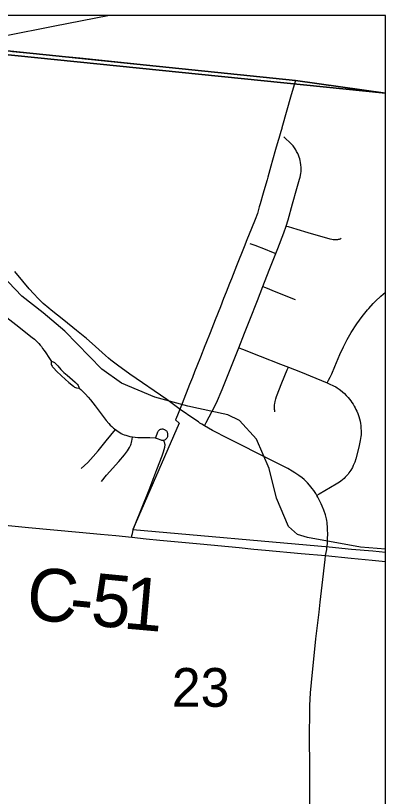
# Model space of a CAD drawing. Extents: x 0 to 34, y 0 to 22.
# Drawn here: x 8.313 to 8.712, y 20.263 to 21.106 of the extents above; entities that cross this region are included whole.
import ezdxf

# ---------------------------------------------------------------- set-up
doc = ezdxf.new("R2010")
doc.units = 0
for name, color, linetype in [('GM_X_City_Street', 7, 'Continuous'), ('GM_X_Corporation', 7, 'Continuous'), ('GM_X_County_Road', 7, 'Continuous'), ('GM_X_County_Road_Text', 7, 'Continuous'), ('GM_X_Interstate_Route', 7, 'Continuous'), ('GM_X_Minor_River', 7, 'Continuous'), ('GM_X_Section_Text', 7, 'Continuous')]:
    doc.layers.add(name, color=color, linetype=linetype)

msp = doc.modelspace()

# ---------------------------------------------------------------- linework, layer by layer
at = {"layer": 'GM_X_City_Street'}
for points in [[(8.51668, 20.66289), (8.5187, 20.66664), (8.52515, 20.6786), (8.52968, 20.6878), (8.53587, 20.70225), (8.55364, 20.74723), (8.55986, 20.76297), (8.56561, 20.7774), (8.57394, 20.79813), (8.57968, 20.8133), (8.5814, 20.81786), (8.58741, 20.83288), (8.5937, 20.84907), (8.5958, 20.85446), (8.60235, 20.87145), (8.60472, 20.87865), (8.60695, 20.88539), (8.61178, 20.90245), (8.6165, 20.91928), (8.61933, 20.92925), (8.61991, 20.93156), (8.62065, 20.93531), (8.62088, 20.93739), (8.621, 20.9397), (8.62095, 20.9417), (8.62076, 20.94489), (8.62046, 20.94735), (8.62008, 20.94924), (8.61955, 20.95123), (8.61895, 20.95313), (8.61805, 20.95532), (8.6173, 20.95697), (8.61615, 20.95927), (8.61534, 20.96078), (8.61461, 20.96197), (8.61393, 20.96297), (8.61308, 20.96419), (8.61234, 20.9651), (8.61128, 20.96624), (8.60955, 20.96799), (8.60346, 20.9738), (8.60225, 20.97493)], [(8.60472, 20.87865), (8.60708, 20.87797), (8.61638, 20.87532), (8.62825, 20.87166), (8.6521, 20.86477), (8.65396, 20.86437), (8.65573, 20.86414), (8.65749, 20.86399), (8.65873, 20.86397), (8.66064, 20.86414), (8.66147, 20.8643), (8.66234, 20.86455), (8.66314, 20.86484), (8.66438, 20.86544)], [(8.56585, 20.85991), (8.57112, 20.85799), (8.58211, 20.85358), (8.58908, 20.85086), (8.5937, 20.84907)], [(8.26292, 20.8211), (8.26641, 20.81677), (8.2702, 20.8118), (8.27768, 20.80174), (8.27887, 20.80025), (8.28028, 20.79864), (8.28176, 20.79723), (8.28354, 20.79567), (8.29194, 20.78906), (8.3036, 20.78), (8.31648, 20.76974), (8.32398, 20.76383), (8.33097, 20.75829), (8.33325, 20.75629), (8.33506, 20.75474), (8.3367, 20.75317), (8.33806, 20.75174), (8.33946, 20.75009), (8.34082, 20.74837), (8.34213, 20.74652), (8.34384, 20.74408), (8.34559, 20.7416), (8.34886, 20.73658), (8.35165, 20.7323)], [(8.57968, 20.8133), (8.58145, 20.81259), (8.58445, 20.81139), (8.59193, 20.80826), (8.61465, 20.79943)], [(8.64908, 20.70924), (8.6507, 20.71229), (8.65228, 20.71546), (8.65406, 20.71916), (8.65729, 20.72688), (8.6627, 20.73983), (8.66663, 20.74829), (8.67063, 20.75601), (8.67501, 20.76354), (8.68108, 20.77294), (8.68688, 20.78104), (8.69117, 20.78647), (8.69244, 20.78798), (8.69399, 20.78968), (8.69887, 20.7951), (8.70109, 20.79732), (8.70712, 20.8029), (8.71189, 20.80715)], [(8.55364, 20.74723), (8.55771, 20.7456), (8.57673, 20.73799), (8.59873, 20.72944), (8.60722, 20.72613), (8.62017, 20.72108), (8.63689, 20.71433), (8.64908, 20.70924), (8.65136, 20.70828), (8.65609, 20.70602), (8.65832, 20.70482), (8.65981, 20.70393), (8.66188, 20.70255), (8.66363, 20.70124), (8.66556, 20.69962), (8.66764, 20.69774), (8.66957, 20.6958), (8.67165, 20.69348), (8.67319, 20.69164), (8.67448, 20.69004), (8.67585, 20.68812), (8.67705, 20.68631), (8.67826, 20.68426), (8.67939, 20.68217), (8.68018, 20.68055), (8.68097, 20.67878), (8.68202, 20.67617), (8.68315, 20.67305), (8.68398, 20.67031), (8.68455, 20.66796), (8.68506, 20.66525), (8.68532, 20.66338), (8.68553, 20.66111), (8.68576, 20.65667), (8.68561, 20.65321), (8.68541, 20.65119), (8.68479, 20.64718), (8.68332, 20.63987), (8.68004, 20.62719), (8.67882, 20.62359), (8.678, 20.62146), (8.67733, 20.61994), (8.67633, 20.61793), (8.67457, 20.61502), (8.6726, 20.61204), (8.67163, 20.61078), (8.6699, 20.60872), (8.66869, 20.60742), (8.6673, 20.60608), (8.66575, 20.60473), (8.66386, 20.60325), (8.66239, 20.60217), (8.65883, 20.59985), (8.64037, 20.589), (8.63794, 20.58756)], [(8.35165, 20.7323), (8.35149, 20.73156), (8.35137, 20.73082), (8.35137, 20.73004), (8.35146, 20.72921), (8.35178, 20.72831), (8.35236, 20.72745), (8.35299, 20.72664), (8.35429, 20.72511), (8.35725, 20.7219), (8.36256, 20.71682), (8.3706, 20.70983), (8.37538, 20.70554), (8.37644, 20.70476), (8.37755, 20.70423), (8.3787, 20.7039), (8.38147, 20.70348)], [(8.35165, 20.7323), (8.35252, 20.73218), (8.35344, 20.73197), (8.3543, 20.73164), (8.35494, 20.73119), (8.35565, 20.73057), (8.35643, 20.72971), (8.3584, 20.72757), (8.36197, 20.72363), (8.36517, 20.72058), (8.36855, 20.71748), (8.3771, 20.71019), (8.37837, 20.70912), (8.37932, 20.70813), (8.37991, 20.70737), (8.38034, 20.70657), (8.38073, 20.70561), (8.38147, 20.70348)], [(8.59279, 20.67789), (8.59253, 20.67936), (8.59237, 20.68033), (8.59224, 20.68139), (8.59216, 20.68203), (8.59213, 20.68276), (8.59212, 20.68421), (8.59229, 20.6857), (8.59253, 20.68697), (8.59297, 20.68905), (8.59376, 20.69197), (8.59461, 20.69462), (8.60026, 20.70914), (8.60605, 20.7233), (8.60722, 20.72613)], [(8.38147, 20.70348), (8.3833, 20.70197), (8.38526, 20.70024), (8.38831, 20.69719), (8.39139, 20.6938), (8.39389, 20.6909), (8.39883, 20.68459), (8.41075, 20.66879), (8.41345, 20.66545), (8.41509, 20.66371), (8.41677, 20.66215), (8.41879, 20.66034), (8.42072, 20.65878)], [(8.38382, 20.61666), (8.39079, 20.62319), (8.3967, 20.62967), (8.40195, 20.63602), (8.41079, 20.64676), (8.42072, 20.65878)], [(8.42072, 20.65878), (8.42207, 20.65779), (8.42363, 20.65675), (8.42559, 20.6555), (8.42693, 20.65471), (8.42839, 20.65401), (8.43011, 20.65329), (8.43196, 20.65268), (8.43399, 20.652), (8.4364, 20.65139), (8.43896, 20.65089)], [(8.47295, 20.64737), (8.47392, 20.64778), (8.47453, 20.64813), (8.47512, 20.64853), (8.47568, 20.64902), (8.47619, 20.64955), (8.47659, 20.65017), (8.4769, 20.6508), (8.47713, 20.65145), (8.47729, 20.65214), (8.47739, 20.65292), (8.47736, 20.65368), (8.47719, 20.65456), (8.47696, 20.6552), (8.4767, 20.65586), (8.47641, 20.65645), (8.47603, 20.65702), (8.47557, 20.65757), (8.47504, 20.65799), (8.47451, 20.65832), (8.47393, 20.65861), (8.47286, 20.65894), (8.47215, 20.6591), (8.47134, 20.6592), (8.47063, 20.65915), (8.46978, 20.659), (8.46897, 20.65877), (8.4683, 20.65839), (8.46726, 20.65754), (8.46683, 20.65706), (8.46645, 20.65643), (8.46613, 20.65585), (8.46384, 20.65008)], [(8.40553, 20.60275), (8.41104, 20.60947), (8.42427, 20.62431), (8.43032, 20.63138), (8.43362, 20.63587), (8.43482, 20.6377), (8.4359, 20.63957), (8.43663, 20.64098), (8.43725, 20.64237), (8.43765, 20.64345), (8.43802, 20.64472), (8.43839, 20.64653), (8.43864, 20.64822), (8.43896, 20.65089)], [(8.43896, 20.65089), (8.44188, 20.65065), (8.4449, 20.65041), (8.44869, 20.65024), (8.45797, 20.65009), (8.46339, 20.6498), (8.4638, 20.64975), (8.46403, 20.64973), (8.46469, 20.64961), (8.46559, 20.64932), (8.46966, 20.64763), (8.47042, 20.64741), (8.47104, 20.6473), (8.4717, 20.64728), (8.47295, 20.64737)], [(8.43823, 20.54259), (8.43848, 20.54435), (8.43899, 20.5467), (8.43989, 20.55047), (8.44202, 20.55645), (8.45721, 20.59387), (8.4622, 20.60709), (8.46551, 20.61564), (8.47099, 20.63063), (8.47239, 20.63461), (8.4733, 20.63737), (8.47401, 20.63999), (8.47416, 20.6409), (8.4742, 20.64168), (8.4742, 20.64246), (8.47408, 20.64328), (8.47392, 20.64407), (8.47367, 20.64493), (8.47338, 20.64604), (8.47295, 20.64737)]]:
    msp.add_lwpolyline(points, dxfattribs=at)
at = {"layer": 'GM_X_Corporation'}
for points in [[(8.71189, 14.30587), (8.71189, 21.10587), (4.05187, 21.10587)], [(8.71189, 14.30587), (8.71189, 21.02216), (8.61486, 21.03591), (8.24427, 21.07383), (8.1735, 21.08097), (8.1315, 21.08535), (8.11104, 21.08726), (7.91119, 21.10587), (4.05187, 21.10587)], [(8.30961, 21.06701), (8.38217, 21.06041), (8.61486, 21.03592), (8.61036, 21.02015), (8.60025, 20.98476), (8.60003, 20.98398), (8.59911, 20.98073), (8.59696, 20.97312), (8.59632, 20.97091), (8.59352, 20.96113), (8.59028, 20.94979), (8.58839, 20.94316), (8.58502, 20.93135), (8.58423, 20.92859), (8.58184, 20.92023), (8.58007, 20.91402), (8.57678, 20.90248), (8.57591, 20.89945), (8.57548, 20.89795), (8.5738, 20.89203), (8.57126, 20.88563), (8.56428, 20.86802), (8.56334, 20.86565), (8.56257, 20.8637), (8.55966, 20.85635), (8.55141, 20.83555), (8.54583, 20.82147), (8.54383, 20.81643), (8.54025, 20.80738), (8.53742, 20.80023), (8.53396, 20.7915), (8.52839, 20.77745), (8.52281, 20.76336), (8.51816, 20.75163), (8.51722, 20.74928), (8.51239, 20.73708), (8.51164, 20.73519), (8.50613, 20.72128), (8.50368, 20.71511), (8.50074, 20.70768), (8.49256, 20.68703), (8.48751, 20.67429), (8.48549, 20.6692), (8.48934, 20.66579), (8.43934, 20.55075), (8.65139, 20.53237), (8.67553, 20.52977), (8.6983, 20.52786), (8.69842, 20.52785), (8.71189, 20.52655), (8.71189, 21.10587), (8.10417, 21.10587)]]:
    msp.add_lwpolyline(points, dxfattribs=at)
for points in [[(8.71189, 21.02216), (8.71189, 21.10587), (7.91119, 21.10587), (8.11104, 21.08726), (8.1315, 21.08535), (8.1735, 21.08097), (8.24427, 21.07383), (8.61486, 21.03591)], [(8.71189, 21.0221), (8.71189, 21.10587), (8.11564, 21.10587), (8.11355, 21.08279)], [(8.71189, 20.00282), (8.71189, 21.0221), (8.11355, 21.08279), (8.01264, 20.06664)]]:
    msp.add_lwpolyline(points, close=True, dxfattribs=at)
at = {"layer": 'GM_X_County_Road'}
for points in [[(8.47599, 20.69146), (8.43622, 20.71862), (8.42291, 20.72822), (8.41572, 20.73375), (8.41326, 20.7358), (8.40983, 20.73888), (8.39576, 20.75185), (8.38949, 20.75732), (8.37873, 20.76597), (8.36519, 20.7768), (8.35123, 20.78779), (8.34884, 20.78976), (8.34278, 20.79508), (8.33723, 20.8005), (8.33256, 20.80542), (8.32764, 20.8108), (8.32065, 20.81908), (8.31231, 20.82953)], [(8.49062, 20.68058), (8.48629, 20.68369), (8.47599, 20.69146)], [(8.51668, 20.66289), (8.51376, 20.66466), (8.51182, 20.6659), (8.51021, 20.66701), (8.50532, 20.67029), (8.49062, 20.68058)], [(8.63794, 20.58756), (8.63673, 20.58975), (8.63472, 20.59291), (8.63294, 20.59534), (8.63017, 20.59879), (8.62788, 20.60145), (8.62626, 20.60312), (8.62438, 20.60494), (8.62201, 20.60689), (8.61861, 20.6094), (8.61431, 20.61223), (8.61132, 20.61399), (8.6065, 20.61663), (8.58867, 20.62571), (8.54225, 20.64913), (8.52548, 20.65787), (8.51668, 20.66289)], [(8.6487, 20.53039), (8.64931, 20.53577), (8.64948, 20.5412), (8.64965, 20.54594), (8.64957, 20.55094), (8.6494, 20.55429), (8.6492, 20.55673), (8.64896, 20.55852), (8.6486, 20.56077), (8.64823, 20.56252), (8.64715, 20.56663), (8.64534, 20.57197), (8.64374, 20.57606), (8.64258, 20.57859), (8.64152, 20.5809), (8.63894, 20.58574), (8.63794, 20.58756)], [(8.29421, 20.55636), (8.32694, 20.55312), (8.38147, 20.548), (8.40446, 20.54595), (8.42099, 20.5444), (8.43823, 20.54259)], [(8.43823, 20.54259), (8.45373, 20.54092), (8.4686, 20.53953), (8.51194, 20.53561), (8.55401, 20.53156), (8.57007, 20.52975), (8.58246, 20.52848), (8.62112, 20.52517), (8.64737, 20.52277)], [(8.64167, 20.47231), (8.64389, 20.49067), (8.6469, 20.51846), (8.64737, 20.52277)], [(8.64737, 20.52277), (8.64858, 20.52932), (8.6487, 20.53039)], [(8.64737, 20.52277), (8.67485, 20.51981), (8.69774, 20.51789), (8.71189, 20.51653)], [(8.63024, 20.25418), (8.6303, 20.29766), (8.63016, 20.32376), (8.63019, 20.33431), (8.6303, 20.34798), (8.63058, 20.36099), (8.63129, 20.37462), (8.63218, 20.38574), (8.63693, 20.43269), (8.64039, 20.46168), (8.64167, 20.47231)]]:
    msp.add_lwpolyline(points, dxfattribs=at)
at = {"layer": 'GM_X_Interstate_Route'}
msp.add_lwpolyline([(8.24352, 21.0731), (8.2445, 21.0733), (8.3012, 21.08413), (8.35548, 21.09466), (8.41233, 21.10587)], dxfattribs=at)
at = {"layer": 'GM_X_Minor_River'}
msp.add_lwpolyline([(8.71189, 20.52975), (8.68502, 20.53195), (8.62795, 20.54222), (8.61701, 20.54547), (8.60732, 20.55402), (8.59427, 20.58465), (8.58657, 20.61669), (8.57279, 20.64847), (8.55461, 20.66858), (8.54183, 20.67491), (8.51048, 20.68162), (8.49877, 20.68414), (8.46331, 20.69396), (8.4272, 20.70912), (8.40588, 20.72397), (8.36611, 20.76502), (8.3426, 20.78485), (8.31982, 20.80277), (8.26261, 20.86276)], dxfattribs=at)

# ---------------------------------------------------------------- texts
at = {"layer": 'GM_X_County_Road_Text'}
for s, rotation, p in [('C', 354.39019, (8.32306, 20.45445)), ('5', 354.4944, (8.39283, 20.4476)), ('1', 354.90014, (8.42811, 20.4442)), ('-', 354.40259, (8.36951, 20.44989))]:
    msp.add_text(s, height=0.05682, rotation=rotation, dxfattribs=at).set_placement(p)
at = {"layer": 'GM_X_Section_Text'}
msp.add_text('23', height=0.041856, rotation=0.00001, dxfattribs=at).set_placement((8.48155, 20.35946))

doc.saveas('drawing.dxf')
